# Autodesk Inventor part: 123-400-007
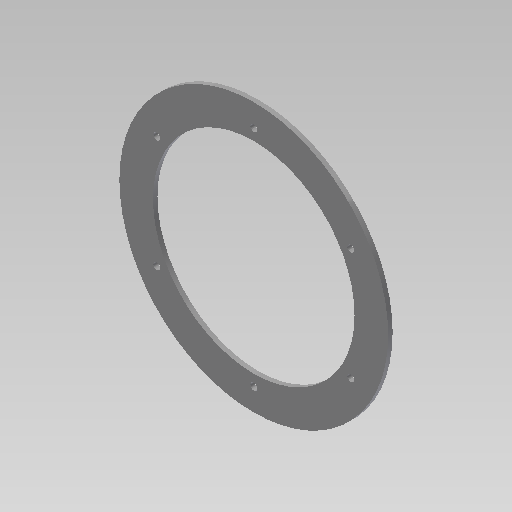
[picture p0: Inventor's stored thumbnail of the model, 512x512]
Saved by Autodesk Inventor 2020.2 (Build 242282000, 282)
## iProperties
Created: 2006-08
Part Number: 123-400-007
Document SubType Name: Modeling
Designer: F.Stasiak
Description: Blokada
Material: Stal
Mass: 9621.59 g
Surface Area: 2810.45 cm^2
Volume: 1225.68 cm^3
Density: 7.85 g/cm^3
Appearance: Stal
Manager: www.cadconsulting.pl
Company: Fabian Stasiak CAD Consulting
KODMAT: 14-2589
Author: F.Stasiak
Subject: Zbiór ćwiczeń. Autodesk Inventor 2020. Kurs podstawowy
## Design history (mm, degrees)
sketch "Szkic1"
  geometry: C1 r 225 at (0, 0); C2 r 300 at (0, 0); 1 further point
  constraints: 2 centre point, 2 coincident
  dimensions: "d0" = 450 diameter of C1; "d1" = 600 diameter of C2
extrude "Wyciągnięcie proste1" new body sketch "Szkic1" distance "d2" = 10; taper "d3" = 0 deg
sketch "Szkic2"
  geometry: L1 (0, 275)-(0, 225); 3 further points
  constraints: 2 end point, 2 vertical alignment, 1 midpoint, 1 point on line, 1 vertical, 2 other
hole "Otwór1" sketch "Szkic2" at (0, 250) diameter "d4" = 15.5; stored, may be unused: countersink angle "d8" = 90 deg, drill point angle "d10" = 118 deg; dims "d5" = 6, "d6" = 4, "d7" = 2, "d9" = 8
pattern_circular "Szyk kołowy1" dims angle "d12" = 360 deg
node "Bryła1"
node "Korpusy bryłowe"
node "Korpusy powierzchniowe"
node "Odniesienie1"
